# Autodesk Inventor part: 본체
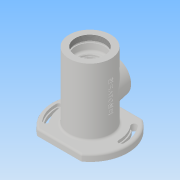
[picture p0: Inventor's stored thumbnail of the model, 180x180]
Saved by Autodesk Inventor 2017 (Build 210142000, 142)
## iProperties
Part Number: 본체
Material: 일반
Document SubType Name: Modeling
Designer: user
Density: 1 g/cm^3
Appearance: 기본값
Author: user
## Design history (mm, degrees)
sketch "스케치1"
  geometry: L1 (-33.985, 47)-(33.985, 47); L2 (33.985, 47)-(33.985, -47); L3 (33.985, -47)-(-33.985, -47); L4 (-33.985, -47)-(-33.985, 47); L5 (-33.985, 47)-(33.985, -47); L6 (33.985, 47)-(-33.985, -47); L7 (0, 0)-(0, 47); L8 (0, 0)-(48, 0); L9 (0, 0)-(36.77, 30.854); L10 (-58, 0)-(58, 0); L11 (0, 0)-(-36.77, -30.854); L12 (0, 0)-(-48, 0); A1 r 58 centre (0, 0) between (33.985, -47) and (33.985, 47); A2 r 58 centre (0, 0) between (-33.985, 47) and (-33.985, -47); A3 r 48 centre (0, 0) between (36.77, 30.854) and (-48, 0); A4 r 48 centre (0, 0) between (48, 0) and (36.77, 30.854); A5 r 52 centre (0, 0) between (52, 0) and (39.834, 33.425); A6 r 44 centre (0, 0) between (44, 0) and (33.706, 28.283); A7 r 4 centre (48, 0) between (44, 0) and (52, 0); A8 r 4 centre (36.77, 30.854) between (39.834, 33.425) and (33.706, 28.283); A9 r 48 centre (0, 0) between (-48, 0) and (-36.77, -30.854); A10 r 52 centre (0, 0) between (-52, 0) and (-39.834, -33.425); A11 r 44 centre (0, 0) between (-44, 0) and (-33.706, -28.283); A12 r 4 centre (-48, 0) between (-44, 0) and (-52, 0); A13 r 4 centre (-36.77, -30.854) between (-39.834, -33.425) and (-33.706, -28.283); 4 further points
  constraints: 29 point on circle, 24 end point, 13 centre point, 8 tangent, 6 midpoint, 4 coincident, 4 horizontal alignment, 2 parallel, 1 horizontal, 1 perpendicular, 1 point on line
  dimensions: "d5" = 94 distance of L1.end L2.end; "d6" = 58 radius of A1; "d7" = 58 radius of A2; "d8" = 96 diameter of A3; "d9" = 40 deg angle of L8 L9; "d10" = 8 diameter of A7; "d11" = 40 deg angle of L12 L11; "d12" = 8 diameter of A13
extrude "돌출1" new body sketch "스케치1" distance "d13" = 13; taper "d14" = 0 deg
sketch "스케치2"
  geometry: C1 r 32 at (0, 0); A1 r 52 centre (0, 0) between (52, 0) and (39.834, 33.425) reference
  constraints: 1 centre point, 1 coincident
  dimensions: "d15" = 64 diameter of C1
extrude "돌출2" join sketch "스케치2" distance "d16" = 102; taper "d17" = 0 deg
sketch "스케치3"
  geometry: L1 (32, 115)-(-32, 115) reference; L2 (0, 0)-(0, 115); L3 (0, 115)-(-22.5, 115); L4 (-22.5, 115)-(-22.5, 107); L5 (-22.5, 107)-(-24, 107); L6 (-24, 107)-(-24, 104); L7 (-24, 104)-(-22.5, 104); L8 (-22.5, 104)-(-22.5, 93); L9 (-22.5, 93)-(-17.5, 93); L10 (-17.5, 93)-(-17.5, 90.75); L11 (-17.5, 90.75)-(-18.5, 90.75); L12 (-18.5, 90.75)-(-18.5, 89); L13 (-18.5, 89)-(-17.5, 89); L14 (-17.5, 89)-(-17.5, 78); L15 (-17.5, 78)-(-27, 78); L16 (-27, 78)-(-27, 40); L17 (-27, 40)-(-17.5, 40); L18 (-17.5, 40)-(-17.5, 29); L19 (-17.5, 29)-(-15, 29); L20 (-15, 29)-(-15, 24); L21 (-15, 24)-(-11, 24); L22 (33.985, 0)-(-33.985, 0) reference; L23 (-20, 14)-(-30, 0); L24 (-11, 24)-(-11, 21.3); L25 (-11, 21.3)-(-15, 21.3); L26 (-15, 21.3)-(-15, 14.7); L27 (-15, 14.7)-(-15.404, 14); L28 (-15.404, 14)-(-20, 14)
  constraints: 52 end point, 17 perpendicular, 4 point on line, 2 horizontal, 2 vertical, 1 midpoint
  dimensions: "d18" = 45 diameter of L4 L2; "d19" = 48 diameter of L6 L2; "d20" = 45 diameter of L8 L2; "d21" = 35 diameter of L10 L2; "d22" = 37 diameter of L12 L2; "d23" = 35 diameter of L14 L2; "d24" = 54 diameter of L16 L2; "d25" = 30 diameter of L20 L2; "d28" = 40 diameter of L23.start L2; "d29" = 60 diameter of L23.end L2; "d30" = 5 distance of L19.end L20.end; "d31" = 29 distance between parallel lines of L22 L19; "d32" = 14 distance from line of L22 L23.start; "d33" = 11 distance of L17.end L18.end; "d34" = 11 distance of L13.end L14.end; "d35" = 3 distance of L5.end L6.end; "d36" = 8 distance of L3.end L4.end; "d37" = 22 distance between parallel lines of L1 L9; "d38" = 1.75 distance of L11.end L12.end; "d39" = 4 distance from line of L13.end L9; "d44" = 22 diameter of L24 L2; "d45" = 30 diameter of L26 L2; "d46" = 30 deg angle of L27 L26; "d47" = 0.7 distance from line of L28 L26.end; "d48" = 7.3 distance between parallel lines of L28 L25
revolve "회전1" sketch "스케치3" stored, may be unused: angle "d49" = 360 deg
sketch "스케치4"
  geometry: L1 (33.985, 47)-(-33.985, 47) reference; L2 (-33.985, -47)-(33.985, -47) reference; C1 r 36 at (0, 0); C2 r 30 at (0, 0) reference; A1 r 44 centre (0, 0) between (-33.706, 28.283) and (-44, 0) reference; A2 r 4 centre (48, 0) between (52, 0) and (44, 0) reference; A3 r 52 centre (0, 0) between (39.834, -33.425) and (52, 0) reference; A4 r 4 centre (36.77, -30.854) between (33.706, -28.283) and (39.834, -33.425) reference; A5 r 44 centre (0, 0) between (33.706, -28.283) and (44, 0) reference; A6 r 4 centre (-48, 0) between (-52, 0) and (-44, 0) reference; A7 r 52 centre (0, 0) between (-39.834, 33.425) and (-52, 0) reference; A8 r 4 centre (-36.77, 30.854) between (-33.706, 28.283) and (-39.834, 33.425) reference; A9 r 44 centre (0, 0) between (-33.706, 28.283) and (-44, 0) reference; A10 r 58 centre (0, 0) between (-33.985, 47) and (-33.985, -47) reference; A11 r 58 centre (0, 0) between (33.985, -47) and (33.985, 47) reference
  constraints: 1 centre point, 1 coincident
  dimensions: "d50" = 72 diameter of C1
extrude "돌출3" cut sketch "스케치4" distance "d51" = 3; taper "d52" = 0 deg
sketch "스케치5" dims "d83" = 62
  geometry: A1 r 44 centre (0, 0) between (-33.706, 28.283) and (-44, 0) reference; A2 r 4 centre (-48, 0) between (-52, 0) and (-44, 0) reference; A3 r 52 centre (0, 0) between (-39.834, 33.425) and (-52, 0) reference; A4 r 4 centre (-36.77, 30.854) between (-33.706, 28.283) and (-39.834, 33.425) reference; A5 r 44 centre (0, 0) between (33.706, -28.283) and (44, 0) reference; A6 r 4 centre (48, 0) between (52, 0) and (44, 0) reference; A7 r 52 centre (0, 0) between (39.834, -33.425) and (52, 0) reference; A8 r 4 centre (36.77, -30.854) between (33.706, -28.283) and (39.834, -33.425) reference; A9 r 45.75 centre (0, 0) between (35.047, -29.408) and (45.75, 0); A10 r 2.25 centre (36.77, -30.854) between (35.047, -29.408) and (38.494, -32.3); A11 r 50.25 centre (0, 0) between (38.494, -32.3) and (50.25, 0); A12 r 2.25 centre (48, 0) between (50.25, 0) and (45.75, 0); A13 r 2.25 centre (-48, 0) between (-50.25, 0) and (-45.75, 0); A14 r 45.75 centre (0, 0) between (-35.047, 29.408) and (-45.75, 0); A15 r 2.25 centre (-36.77, 30.854) between (-35.047, 29.408) and (-38.494, 32.3); A16 r 50.25 centre (0, 0) between (-38.494, 32.3) and (-50.25, 0)
  constraints: 16 point on circle, 8 centre point, 6 other
  dimensions: "d53" = 1.75 radial gap between concentric circles of A5 A9; "d54" = 1.75 radial gap between concentric circles of A3 A16
extrude "돌출4" join sketch "스케치5" distance "d55" = 5.6; taper "d56" = 0 deg
sketch "스케치6"
  geometry: C1 r 4 at (36.77, 30.854); C2 r 4 at (-36.77, -30.854); A1 r 4 centre (-36.77, -30.854) between (-39.834, -33.425) and (-33.706, -28.283) reference; A2 r 4 centre (36.77, 30.854) between (39.834, 33.425) and (33.706, 28.283) reference
  constraints: 2 centre point, 2 coincident
  dimensions: "d57" = 8 diameter of C1; "d58" = 8 diameter of C2
extrude "돌출5" cut sketch "스케치6" stored distance "d59" = 5.6; taper "d60" = 0 deg
node "작업 평면1"
sketch "스케치7"
  geometry: L1 (32, 115)-(-32, 115) reference; C1 r 25 at (0, 59); 1 further point
  constraints: 1 centre point, 1 vertical alignment
  dimensions: "d62" = 50 diameter of C1; "d63" = 56 distance from line of L1 C1.centre
extrude "돌출6" join sketch "스케치7" stored distance "d64" = 5.6; taper "d65" = 10 deg
hole "구멍1" diameter "d68" = 32; stored, may be unused: countersink angle "d72" = 90 deg, drill point angle "d74" = 0 deg; dims "d66" = 10, "d67" = 10, "d69" = 6, "d70" = 4, "d71" = 2, "d73" = 8
sketch "스케치8"
  geometry: L1 (0, 0)-(-20.5, 0); L2 (0, 0)-(20.5, 0); C1 r 25 at (0, 0) reference; A1 r 20.5 centre (0, 0) between (-20.5, 0) and (20.5, 0); 3 further points
  constraints: 4 end point, 3 coincident, 2 point on circle, 1 centre point
  dimensions: "d75" = 41 diameter of A1
hole "구멍2" sketch "스케치8" at (-20.5, 0), (20.5, 0) diameter "d76" = 2.621; stored, may be unused: countersink angle "d80" = 90 deg, drill point angle "d82" = 118 deg; dims "d77" = 6, "d78" = 4, "d79" = 2, "d81" = 8
node "작업 평면2"
sketch "스케치9"
  geometry: L1 (3.602, 76.887)-(3.602, 27.113); L2 (3.602, 27.113)-(-3.602, 27.113); L3 (-3.602, 27.113)-(-3.602, 76.887); L4 (-3.602, 76.887)-(3.602, 76.887); L5 (3.602, 76.887)-(-3.602, 27.113); L6 (47, -10)-(-47, -10) reference; 2 further points
  constraints: 2 end point, 1 midpoint, 1 vertical alignment, 2 other
  dimensions: "d83" = 62 distance from line of point (0, 52) L6
feature "엠보싱1" sketch "스케치9" dims "d5" = 94, "d6" = 58, "d7" = 58, "d8" = 96, "d9" = 40 deg, "d10" = 8, "d11" = 40 deg, "d12" = 8, "d84" = 0.5, "d85" = 0
chamfer "모따기1" distance "d86" = 1; stored, may be unused: second distance "d87" = 2, angle "d88" = 45 deg
chamfer "모따기2" distance "d89" = 1; stored, may be unused: second distance "d90" = 2, angle "d91" = 45 deg
feature "스레드1" dims "d92" = 10, "d93" = 0
fillet "모깎기1" dims "d94" = 0.6
fillet "모깎기2" dims "d95" = 0.5
fillet "모깎기3" dims "d96" = 3
chamfer "모따기3" distance "d97" = 1; stored, may be unused: second distance "d98" = 2, angle "d99" = 45 deg
chamfer "모따기4" distance "d100" = 1; stored, may be unused: second distance "d101" = 2, angle "d102" = 45 deg
fillet "모깎기4" dims "d103" = 3
fillet "모깎기6" dims "d105" = 3
fillet "모깎기7" dims "d106" = 3
fillet "모깎기8" dims "d107" = 3
node "솔리드1"
node "투영된 루프1"
other parameters: "d61" = 38
